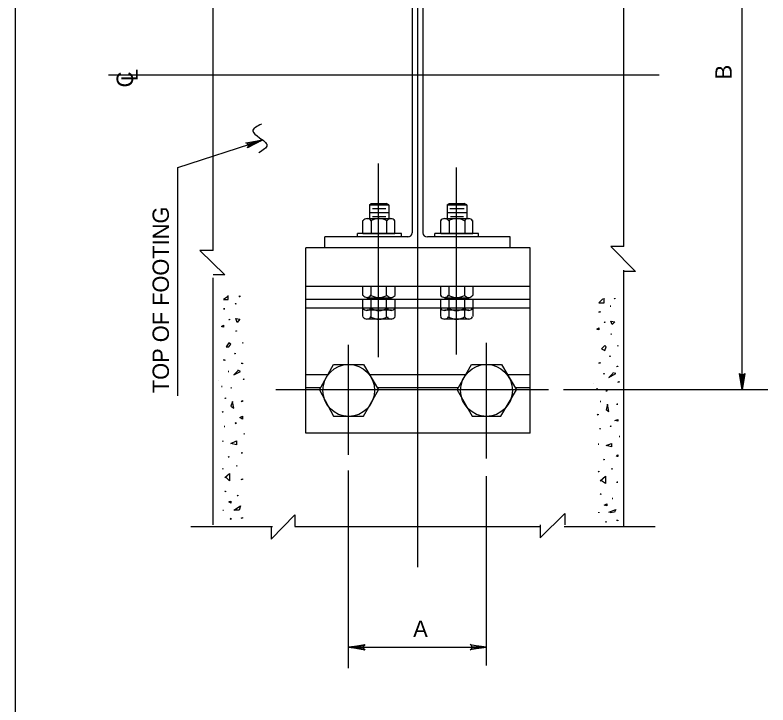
# Model space of a CAD drawing. Extents: x 637580 to 641008, y 294594 to 295782.
# Drawn here: x 640143.3 to 640281.8, y 294941.3 to 295068.2 of the extents above; entities that cross this region are included whole.
import ezdxf

# ---------------------------------------------------------------- set-up
doc = ezdxf.new("R2010")
doc.units = 0
for name, color, linetype in [('1', 7, 'Continuous'), ('2', 7, 'Continuous'), ('3', 7, 'Continuous')]:
    doc.layers.add(name, color=color, linetype=linetype)

# ---------------------------------------------------------------- blocks, each defined once
blk = doc.blocks.new('RARROW')
at = {"layer": '3'}
blk.add_lwpolyline([(-2.2695, 0.285), (-2.184875, 0.12075), (0, 0), (-2.2695, 0.285), (-2.38575, 0.384625), (0, 0), (-2.183125, -0.108), (-2.262875, -0.2705), (0, 0), (-2.38575, -0.379125), (-2.262875, -0.2705)], dxfattribs=at)

msp = doc.modelspace()

# ---------------------------------------------------------------- linework, layer by layer
at = {"layer": '1'}
msp.add_line((640143.31, 295172.63), (640143.31, 294608.63), dxfattribs=at)
at = {"layer": '2'}
for p, q in [((640217.39, 294966.63), (640217.39, 295153.26)), ((640277.02, 294999.26), (640277.02, 295115.26)), ((640179.77, 295024.88), (640179.77, 295095.13)), ((640255.27, 295025.63), (640255.27, 295093.01)), ((640216.39, 295028.13), (640216.39, 295086.13)), ((640218.39, 295028.13), (640218.39, 295086.13)), ((640261.77, 295057.13), (640160.52, 295057.13)), ((640173.27, 295040.13), (640188.74, 295045.16)), ((640210.14, 295005.26), (640210.14, 295040.88)), ((640173.27, 294998.16), (640173.27, 295040.13)), ((640224.52, 295005.76), (640224.52, 295040.13)), ((640208.52, 295033.26), (640208.77, 295033.51)), ((640208.52, 295033.26), (640208.52, 295030.76)), ((640208.52, 295033.26), (640212.02, 295033.26)), ((640208.77, 295033.51), (640211.64, 295033.51)), ((640212.02, 295033.26), (640211.64, 295033.51)), ((640212.02, 295033.26), (640212.02, 295030.76)), ((640222.77, 295033.26), (640223.14, 295033.51)), ((640222.77, 295033.26), (640222.77, 295030.76)), ((640222.77, 295033.26), (640226.39, 295033.26)), ((640223.14, 295033.51), (640225.89, 295033.51)), ((640226.39, 295033.26), (640225.89, 295033.51)), ((640226.39, 295033.26), (640226.39, 295030.76)), ((640208.52, 295031.88), (640212.02, 295031.88)), ((640209.02, 295032.63), (640211.52, 295032.63)), ((640222.77, 295031.88), (640226.39, 295031.88)), ((640223.27, 295032.63), (640225.89, 295032.63)), ((640208.02, 295030.76), (640212.52, 295030.76)), ((640209.02, 295031.13), (640211.52, 295031.13)), ((640210.14, 295030.76), (640210.14, 295030.76)), ((640210.14, 295030.76), (640210.14, 295030.76)), ((640222.27, 295030.76), (640226.77, 295030.76)), ((640223.39, 295031.13), (640225.77, 295031.13)), ((640224.52, 295030.76), (640224.52, 295030.76)), ((640224.52, 295030.76), (640224.52, 295030.76)), ((640207.27, 295028.01), (640207.27, 295030.38)), ((640208.77, 295030.38), (640208.77, 295028.01)), ((640211.64, 295030.38), (640211.64, 295028.01)), ((640213.14, 295028.01), (640213.14, 295030.38)), ((640221.64, 295028.01), (640221.64, 295030.38)), ((640223.14, 295030.38), (640223.14, 295028.01)), ((640226.02, 295030.38), (640226.02, 295028.01)), ((640227.52, 295028.01), (640227.52, 295030.38)), ((640214.39, 295028.01), (640206.27, 295028.01)), ((640206.27, 295027.38), (640206.27, 295028.01)), ((640207.27, 295028.01), (640213.14, 295028.01)), ((640210.14, 295028.01), (640210.14, 295028.01)), ((640210.14, 295028.01), (640210.14, 295028.01)), ((640214.39, 295027.38), (640214.39, 295028.01)), ((640228.52, 295028.01), (640220.52, 295028.01)), ((640220.52, 295027.38), (640220.52, 295028.01)), ((640221.64, 295028.01), (640227.52, 295028.01)), ((640224.52, 295028.01), (640224.52, 295028.01)), ((640224.52, 295028.01), (640224.52, 295028.01)), ((640224.52, 295028.01), (640224.52, 295028.01)), ((640228.52, 295027.38), (640228.52, 295028.01)), ((640200.27, 295025.38), (640200.27, 295027.38)), ((640215.64, 295027.38), (640200.27, 295027.38)), ((640234.39, 295027.38), (640219.14, 295027.38)), ((640234.39, 295025.38), (640234.39, 295027.38)), ((640238.02, 295025.38), (640196.77, 295025.38)), ((640196.77, 294991.26), (640196.77, 295025.38)), ((640238.02, 294991.26), (640238.02, 295025.38)), ((640255.27, 295025.63), (640252.89, 295025.63)), ((640252.89, 295025.63), (640257.39, 295021.01)), ((640179.77, 295024.88), (640177.27, 295024.88)), ((640177.27, 295024.88), (640181.89, 295020.38)), ((640255.27, 294974.01), (640255.27, 295021.26)), ((640257.39, 295021.01), (640255.27, 295021.01)), ((640181.89, 295020.38), (640179.77, 295020.38)), ((640179.77, 294974.38), (640179.77, 295019.88)), ((640238.02, 295018.26), (640196.77, 295018.26)), ((640213.14, 295018.26), (640207.27, 295018.26)), ((640207.27, 295016.63), (640207.27, 295018.26)), ((640208.77, 295016.63), (640208.77, 295018.26)), ((640210.14, 295018.26), (640210.14, 295018.26)), ((640210.14, 295018.26), (640210.14, 295018.26)), ((640211.64, 295016.63), (640211.64, 295018.26)), ((640213.14, 295018.26), (640213.14, 295016.63)), ((640227.52, 295018.26), (640221.64, 295018.26)), ((640221.64, 295016.63), (640221.64, 295018.26)), ((640223.14, 295016.63), (640223.14, 295018.26)), ((640224.52, 295018.26), (640224.52, 295018.26)), ((640224.52, 295018.26), (640224.52, 295018.26)), ((640226.02, 295016.63), (640226.02, 295018.26)), ((640227.52, 295018.26), (640227.52, 295016.63)), ((640238.02, 295015.88), (640196.77, 295015.88)), ((640213.14, 295015.88), (640207.27, 295015.88)), ((640207.27, 295014.26), (640207.27, 295015.88)), ((640212.52, 295016.13), (640208.02, 295016.13)), ((640208.77, 295014.26), (640208.77, 295015.88)), ((640210.14, 295015.88), (640210.14, 295015.88)), ((640210.14, 295015.88), (640210.14, 295015.88)), ((640211.64, 295014.26), (640211.64, 295015.88)), ((640213.14, 295015.88), (640213.14, 295014.26)), ((640227.52, 295015.88), (640221.64, 295015.88)), ((640221.64, 295014.26), (640221.64, 295015.88)), ((640226.77, 295016.13), (640222.27, 295016.13)), ((640223.14, 295014.26), (640223.14, 295015.88)), ((640224.52, 295015.88), (640224.52, 295015.88)), ((640224.52, 295015.88), (640224.52, 295015.88)), ((640226.02, 295014.26), (640226.02, 295015.88)), ((640227.52, 295015.88), (640227.52, 295014.26)), ((640207.27, 295014.26), (640196.77, 295014.26)), ((640213.14, 295014.26), (640207.27, 295014.26)), ((640207.27, 295012.76), (640207.27, 295014.26)), ((640212.52, 295013.88), (640208.02, 295013.88)), ((640208.77, 295012.63), (640208.77, 295014.26)), ((640210.14, 295014.26), (640210.14, 295014.26)), ((640210.14, 295014.26), (640210.14, 295014.26)), ((640211.64, 295012.76), (640211.64, 295014.26)), ((640213.14, 295014.26), (640213.14, 295012.76)), ((640221.64, 295014.26), (640213.14, 295014.26)), ((640227.52, 295014.26), (640221.64, 295014.26)), ((640221.64, 295012.76), (640221.64, 295014.26)), ((640226.77, 295013.88), (640222.27, 295013.88)), ((640223.14, 295012.63), (640223.14, 295014.26)), ((640224.52, 295014.26), (640224.52, 295014.26)), ((640224.52, 295014.26), (640224.52, 295014.26)), ((640226.02, 295012.76), (640226.02, 295014.26)), ((640227.52, 295014.26), (640227.52, 295012.76)), ((640238.02, 295014.26), (640227.52, 295014.26)), ((640212.52, 295012.26), (640208.02, 295012.26)), ((640226.77, 295012.26), (640222.27, 295012.26)), ((640204.64, 294987.26), (640204.64, 295007.51)), ((640230.02, 294986.63), (640230.02, 295007.88)), ((640199.27, 294999.26), (640201.89, 295003.88)), ((640201.89, 295003.88), (640207.39, 295003.88)), ((640207.39, 295003.88), (640210.14, 294999.26)), ((640224.64, 294999.26), (640227.27, 295003.88)), ((640227.27, 295003.88), (640232.77, 295003.88)), ((640232.77, 295003.88), (640235.52, 294999.26)), ((640200.89, 295002.01), (640196.77, 295002.01)), ((640226.27, 295002.01), (640208.52, 295002.01)), ((640238.02, 295002.01), (640233.89, 295002.01)), ((640180.77, 295000.88), (640180.77, 295000.88)), ((640249.77, 295000.38), (640249.77, 295000.38)), ((640241.39, 294999.26), (640191.27, 294999.26)), ((640199.52, 294999.63), (640196.77, 294999.63)), ((640199.27, 294999.26), (640201.89, 294994.38)), ((640204.64, 294999.26), (640204.64, 294999.26)), ((640204.64, 294999.26), (640204.64, 294999.26)), ((640204.64, 294999.26), (640204.64, 294999.26)), ((640204.64, 294999.26), (640204.64, 294999.26)), ((640204.64, 294999.26), (640204.64, 294999.26)), ((640207.39, 294994.38), (640210.14, 294999.26)), ((640224.89, 294999.63), (640210.02, 294999.63)), ((640224.64, 294999.26), (640227.39, 294994.38)), ((640230.02, 294999.26), (640230.02, 294999.26)), ((640230.02, 294999.26), (640230.02, 294999.26)), ((640230.02, 294999.26), (640230.02, 294999.26)), ((640230.02, 294999.26), (640230.02, 294999.26)), ((640232.64, 294994.38), (640235.52, 294999.26)), ((640238.02, 294999.63), (640235.27, 294999.63)), ((640281.77, 294999.26), (640244.14, 294999.26)), ((640201.89, 294994.38), (640207.39, 294994.38)), ((640227.39, 294994.38), (640232.64, 294994.38)), ((640238.02, 294991.26), (640196.77, 294991.26)), ((640204.64, 294948.01), (640204.64, 294984.38)), ((640230.02, 294948.51), (640230.02, 294983.38)), ((640239.89, 294972.01), (640244.39, 294976.51)), ((640244.39, 294976.51), (640244.39, 294974.38)), ((640190.39, 294971.76), (640194.77, 294976.26)), ((640194.77, 294976.26), (640194.77, 294974.13)), ((640175.64, 294974.13), (640190.64, 294974.13)), ((640190.39, 294974.13), (640190.39, 294971.76)), ((640194.77, 294974.13), (640239.89, 294974.13)), ((640239.89, 294974.38), (640239.89, 294972.01)), ((640244.27, 294974.13), (640261.02, 294974.13)), ((640204.64, 294951.88), (640230.02, 294951.88))]:
    msp.add_line(p, q, dxfattribs=at)
for points in [[(640182.39, 295016.38), (640181.64, 295015.88), (640182.52, 295015.88), (640182.52, 295016.63)], [(640184.52, 295016.38), (640184.64, 295016.51), (640184.64, 295016.38), (640184.52, 295016.38)], [(640251.39, 295016.01), (640250.64, 295015.26), (640251.64, 295015.26), (640251.64, 295016.13)], [(640253.52, 295016.01), (640253.64, 295016.13), (640253.64, 295016.01), (640253.52, 295016.01)], [(640181.64, 295014.13), (640181.89, 295014.13), (640181.89, 295014.13), (640181.64, 295014.13)], [(640183.77, 295015.13), (640183.89, 295015.13), (640183.89, 295015.01), (640183.77, 295015.13)], [(640252.77, 295014.63), (640252.89, 295014.63), (640252.89, 295014.63), (640252.77, 295014.63)], [(640250.64, 295013.51), (640250.89, 295013.63), (640250.89, 295013.51), (640250.64, 295013.51)], [(640181.27, 295010.88), (640181.64, 295011.13), (640181.64, 295010.76), (640181.27, 295010.88)], [(640182.64, 295012.13), (640182.77, 295012.26), (640182.77, 295012.13), (640182.64, 295012.13)], [(640183.89, 295012.38), (640184.64, 295012.26), (640184.14, 295011.63), (640183.89, 295012.38)], [(640251.64, 295011.63), (640251.77, 295011.76), (640251.77, 295011.63), (640251.64, 295011.63)], [(640252.89, 295011.88), (640253.64, 295011.76), (640253.14, 295011.26), (640252.89, 295011.88)], [(640183.89, 295010.01), (640184.02, 295010.13), (640184.02, 295010.01), (640183.89, 295010.01)], [(640250.27, 295010.38), (640250.64, 295010.63), (640250.64, 295010.26), (640250.27, 295010.38)], [(640252.89, 295009.51), (640253.02, 295009.51), (640253.02, 295009.51), (640252.89, 295009.51)], [(640182.64, 295007.88), (640182.14, 295007.13), (640182.64, 295007.13), (640183.02, 295007.63), (640182.64, 295007.88)], [(640185.14, 295007.88), (640185.27, 295007.88), (640185.27, 295007.88), (640185.14, 295007.88)], [(640251.77, 295007.38), (640251.14, 295006.76), (640251.77, 295006.51), (640252.02, 295007.13), (640251.77, 295007.38)], [(640254.14, 295007.38), (640254.14, 295007.38), (640254.14, 295007.26), (640254.14, 295007.38)], [(640183.64, 295005.88), (640183.77, 295006.01), (640183.77, 295005.88), (640183.64, 295005.88)], [(640181.64, 295004.76), (640181.89, 295004.76), (640181.89, 295004.63), (640181.64, 295004.76)], [(640250.64, 295004.13), (640250.89, 295004.26), (640250.89, 295004.13), (640250.64, 295004.13)], [(640252.64, 295005.38), (640252.77, 295005.51), (640252.77, 295005.38), (640252.64, 295005.38)], [(640184.27, 295002.76), (640183.52, 295002.01), (640184.77, 295002.63), (640184.27, 295002.88)], [(640184.89, 295004.13), (640185.14, 295004.13), (640185.14, 295004.01), (640185.02, 295004.13)], [(640253.89, 295003.51), (640254.14, 295003.63), (640254.14, 295003.51), (640254.02, 295003.51)], [(640182.52, 295002.63), (640182.64, 295002.63), (640182.64, 295002.63), (640182.52, 295002.63)], [(640251.52, 295002.26), (640251.64, 295002.26), (640251.64, 295002.13), (640251.52, 295002.26)], [(640253.27, 295002.26), (640252.52, 295001.51), (640253.77, 295002.26), (640253.27, 295002.38)], [(640185.27, 295001.13), (640185.39, 295001.26), (640185.39, 295001.13), (640185.27, 295001.13)], [(640254.14, 295000.63), (640254.39, 295000.76), (640254.39, 295000.63), (640254.27, 295000.63)], [(640181.27, 294999.88), (640181.39, 294999.88), (640181.39, 294999.88), (640181.27, 294999.88)], [(640183.02, 294999.63), (640183.14, 294999.63), (640183.14, 294999.63), (640183.02, 294999.63)], [(640250.27, 294999.51), (640250.39, 294999.51), (640250.39, 294999.38), (640250.27, 294999.51)], [(640252.02, 294999.01), (640252.14, 294999.26), (640252.14, 294999.01), (640252.02, 294999.01)], [(640181.89, 294997.63), (640182.02, 294997.76), (640182.02, 294997.63), (640181.89, 294997.63)], [(640184.89, 294997.13), (640185.14, 294997.26), (640185.14, 294997.13), (640185.02, 294997.13)], [(640183.52, 294995.88), (640183.27, 294997.13), (640183.02, 294996.26), (640183.52, 294995.88)], [(640250.89, 294997.13), (640251.02, 294997.13), (640251.02, 294997.13), (640250.89, 294997.13)], [(640252.52, 294995.26), (640252.27, 294996.63), (640252.02, 294995.63), (640252.52, 294995.26)], [(640253.89, 294996.63), (640254.14, 294996.63), (640254.14, 294996.63), (640254.02, 294996.63)], [(640181.39, 294995.13), (640181.52, 294995.26), (640181.52, 294995.13), (640181.39, 294995.13)], [(640250.39, 294994.63), (640250.52, 294994.76), (640250.52, 294994.63), (640250.39, 294994.63)], [(640183.77, 294993.13), (640183.89, 294993.26), (640183.89, 294993.01), (640183.77, 294993.13)], [(640184.64, 294994.13), (640185.14, 294994.38), (640185.14, 294993.88), (640184.64, 294994.13)], [(640253.64, 294993.63), (640254.14, 294993.76), (640254.14, 294993.51), (640253.77, 294993.63)], [(640181.77, 294992.51), (640181.89, 294992.51), (640181.89, 294992.51), (640181.77, 294992.51)], [(640250.77, 294992.13), (640250.89, 294992.13), (640250.89, 294992.01), (640250.89, 294992.13)], [(640252.77, 294992.51), (640252.89, 294992.63), (640252.89, 294992.51), (640252.77, 294992.51)], [(640185.39, 294991.13), (640185.52, 294991.13), (640185.52, 294991.13), (640185.39, 294991.13)], [(640254.39, 294990.63), (640254.52, 294990.63), (640254.52, 294990.63), (640254.39, 294990.63)], [(640181.52, 294989.76), (640181.52, 294989.88), (640181.52, 294989.76), (640181.52, 294989.76)], [(640183.02, 294989.38), (640184.02, 294989.88), (640184.02, 294989.13), (640183.02, 294989.38)], [(640250.52, 294989.26), (640250.64, 294989.26), (640250.64, 294989.26), (640250.52, 294989.26)], [(640252.02, 294989.01), (640253.02, 294989.38), (640253.02, 294988.76), (640252.02, 294989.01)], [(640184.89, 294987.63), (640185.14, 294987.63), (640185.14, 294987.63), (640185.02, 294987.63)], [(640182.52, 294986.88), (640182.64, 294987.01), (640182.64, 294986.88), (640182.52, 294986.88)], [(640251.52, 294986.38), (640251.64, 294986.51), (640251.64, 294986.38), (640251.52, 294986.38)], [(640253.89, 294987.01), (640254.14, 294987.26), (640254.14, 294987.01), (640254.02, 294987.01)], [(640184.02, 294985.26), (640184.14, 294985.26), (640184.14, 294985.26), (640184.02, 294985.26)], [(640181.52, 294984.63), (640181.52, 294984.76), (640181.52, 294984.63), (640181.52, 294984.63)], [(640181.89, 294983.13), (640182.77, 294983.88), (640182.77, 294982.51), (640182.14, 294983.13)], [(640250.52, 294984.13), (640250.64, 294984.26), (640250.64, 294984.13), (640250.52, 294984.13)], [(640253.02, 294984.63), (640253.14, 294984.76), (640253.14, 294984.63), (640253.02, 294984.63)], [(640184.89, 294982.76), (640185.14, 294982.88), (640185.14, 294982.76), (640185.02, 294982.76)], [(640250.89, 294982.51), (640251.89, 294983.38), (640251.89, 294982.01), (640251.14, 294982.51)], [(640253.89, 294982.26), (640254.14, 294982.26), (640254.14, 294982.26), (640254.02, 294982.26)], [(640181.89, 294980.63), (640182.02, 294980.63), (640182.02, 294980.51), (640181.89, 294980.63)], [(640184.14, 294979.76), (640184.27, 294979.88), (640184.27, 294979.76), (640184.14, 294979.76)], [(640250.89, 294980.13), (640251.02, 294980.13), (640251.02, 294980.01), (640250.89, 294980.13)], [(640253.14, 294979.26), (640253.27, 294979.26), (640253.27, 294979.26), (640253.14, 294979.26)], [(640182.64, 294978.63), (640183.02, 294978.76), (640183.02, 294978.38), (640182.64, 294978.63)], [(640183.52, 294977.13), (640184.77, 294977.88), (640184.52, 294977.13), (640183.77, 294977.13)], [(640251.64, 294978.01), (640252.14, 294978.26), (640252.14, 294977.88), (640251.77, 294978.01)], [(640181.52, 294977.13), (640181.64, 294977.13), (640181.64, 294977.13), (640181.64, 294977.13)], [(640250.64, 294976.76), (640250.64, 294976.76), (640250.64, 294976.63), (640250.64, 294976.76)], [(640252.52, 294976.76), (640253.77, 294977.26), (640253.52, 294976.76), (640252.77, 294976.63)], [(640182.89, 294975.51), (640183.02, 294975.63), (640183.02, 294975.38), (640182.89, 294975.51)], [(640184.89, 294975.63), (640185.14, 294975.76), (640185.14, 294975.63), (640185.02, 294975.63)], [(640253.89, 294975.26), (640254.14, 294975.26), (640254.14, 294975.13), (640254.02, 294975.26)], [(640251.89, 294974.88), (640252.02, 294975.01), (640252.02, 294974.88), (640251.89, 294974.88)]]:
    msp.add_lwpolyline(points, dxfattribs=at)
for centre, major_axis, start_param, end_param in [((640208.04, 295029.82), (0, -0.928), 2.182491, 4.100694), ((640210.21, 295027.76), (0, -2.99), 2.619197, 3.637846), ((640212.44, 295029.86), (0, -0.892), 2.161446, 4.121739), ((640222.31, 295029.82), (0, -0.928), 2.182491, 4.100694), ((640224.48, 295027.76), (0, -2.99), 2.619197, 3.637846), ((640226.71, 295029.86), (0, -0.892), 2.161446, 4.121739), ((640215.56, 295028.16), (0, 0.794), 3.141593, 4.712389), ((640219.12, 295028.16), (0, -0.794), 4.712389, 6.283185), ((640208.02, 295017.12), (0, -0.881), 5.297777, 7.268594), ((640210.23, 295019.21), (0, -2.98), 5.763742, 6.806911), ((640212.45, 295017.13), (0, -0.893), 5.304946, 7.261424), ((640222.29, 295017.12), (0, -0.881), 5.297777, 7.268594), ((640224.5, 295019.21), (0, -2.98), 5.763742, 6.806911), ((640226.72, 295017.13), (0, -0.893), 5.304946, 7.261424), ((640208.02, 295014.73), (0, -0.881), 5.297777, 7.268594), ((640210.23, 295016.82), (0, -2.98), 5.763742, 6.806911), ((640212.45, 295014.74), (0, -0.893), 5.304946, 7.261424), ((640222.29, 295014.73), (0, -0.881), 5.297777, 7.268594), ((640224.5, 295016.82), (0, -2.98), 5.763742, 6.806911), ((640226.72, 295014.74), (0, -0.893), 5.304946, 7.261424), ((640208.02, 295013.14), (0, -0.881), 5.297777, 7.268594), ((640210.23, 295015.23), (0, -2.98), 5.763742, 6.806911), ((640212.45, 295013.15), (0, -0.893), 5.304946, 7.261424), ((640222.29, 295013.14), (0, -0.881), 5.297777, 7.268594), ((640224.5, 295015.23), (0, -2.98), 5.763742, 6.806911), ((640226.72, 295013.15), (0, -0.893), 5.304946, 7.261424)]:
    msp.add_ellipse(centre, major_axis=major_axis, ratio=0.996388, start_param=start_param, end_param=end_param, dxfattribs=at)
for centre in [(640204.67, 294999.14), (640230.01, 294999.14)]:
    msp.add_ellipse(centre, major_axis=(0, -4.78), ratio=0.996388, dxfattribs=at)
msp.add_spline([(640188.64, 295048.13), (640187.02, 295046.88), (640188.27, 295045.63), (640189.64, 295044.26), (640188.14, 295042.88)], degree=3, dxfattribs=at)

# ---------------------------------------------------------------- block references
for p, xscale, yscale, rotation in [((640188.74, 295045.16), 1.2574347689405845, 1.3092961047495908, 17.94363433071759), ((640277.02, 294999.26), 1.2574347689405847, 1.3092961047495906, -90.00000000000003), ((640204.64, 294951.88), 1.2574347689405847, 1.3092961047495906, 180)]:
    msp.add_blockref('RARROW', p, dxfattribs=dict(at, xscale=xscale, yscale=yscale, rotation=rotation))
at = {"layer": '2', "xscale": 1.2574347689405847, "yscale": 1.3092961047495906}
msp.add_blockref('RARROW', (640230.02, 294951.88), dxfattribs=at)

# ---------------------------------------------------------------- texts
at = {"layer": '1'}
for s, height, p in [('B', 3, (640275.1, 295056.37)), ('C', 3.03, (640165.02, 295054.88)), ('L', 3.03, (640165.89, 295056.01)), ('TOP OF FOOTING', 3, (640171.6, 294998.64))]:
    msp.add_text(s, height=height, rotation=90, dxfattribs=at).set_placement(p)
msp.add_text('A', height=3, dxfattribs=at).set_placement((640216.53, 294953.79))

doc.saveas('drawing.dxf')
